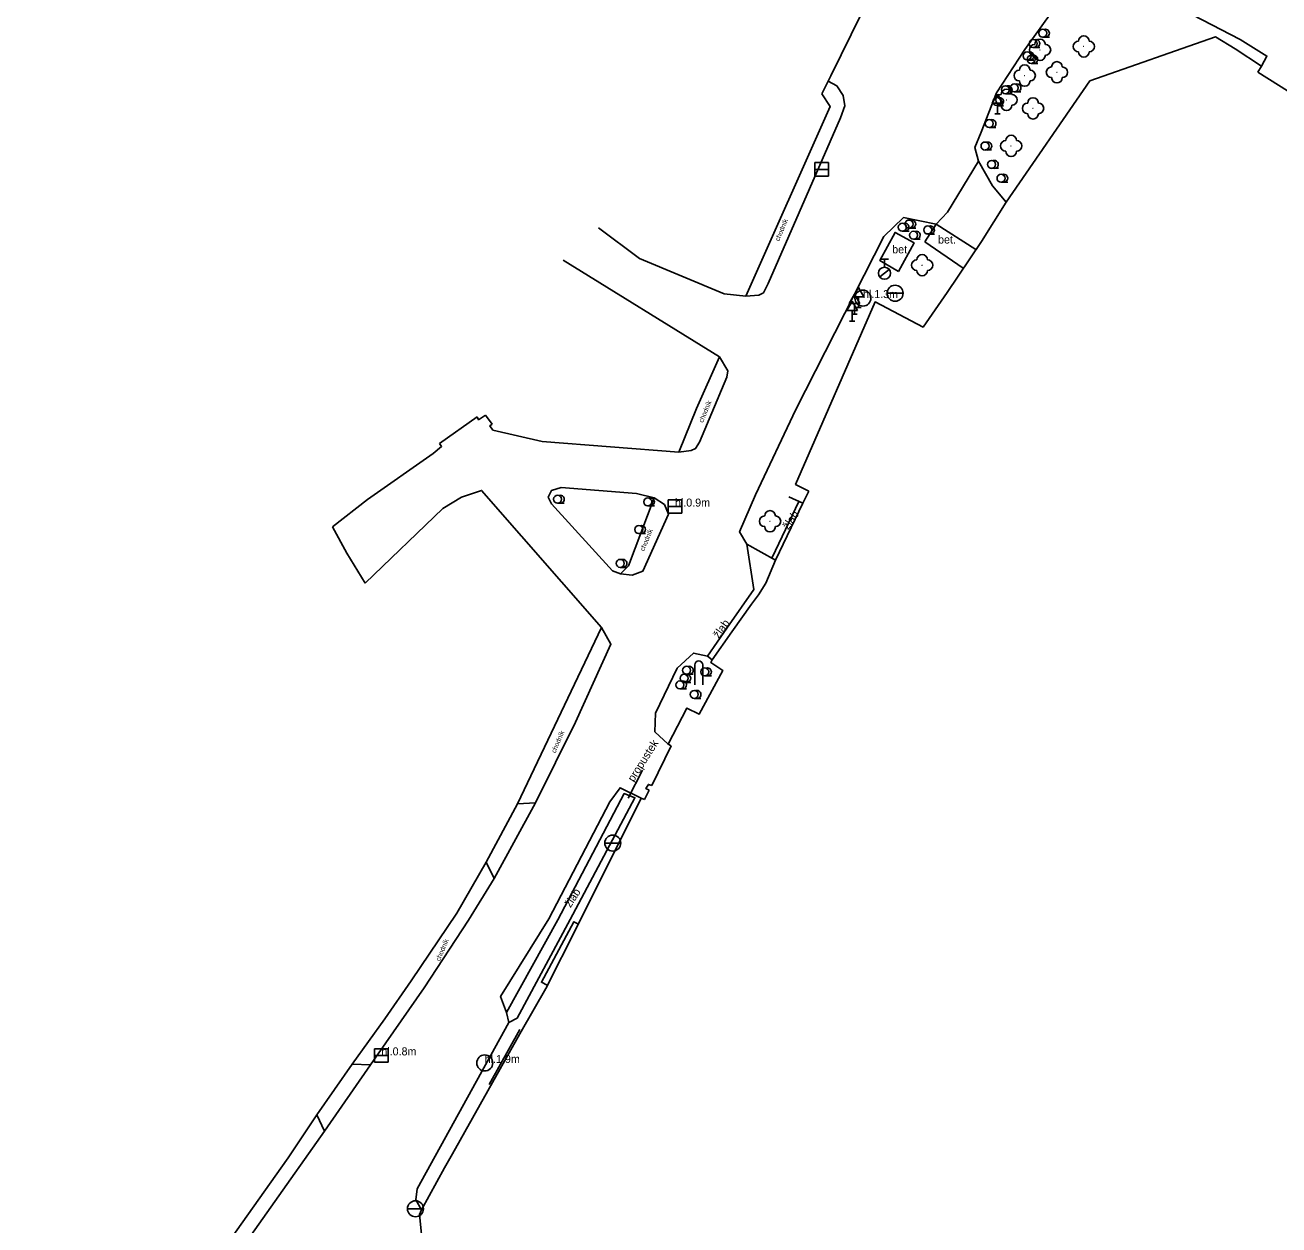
# Model space of a CAD drawing. Extents: x -747135 to -746147, y -1093269 to -1091735.
# Drawn here: x -746683.3 to -746565.8, y -1093037.4 to -1092924.9 of the extents above; entities that cross this region are included whole.
import ezdxf

# ---------------------------------------------------------------- set-up
doc = ezdxf.new("R2010")
doc.units = 0
for name, color, linetype in [('1016', 7, 'Continuous'), ('1029', 7, 'Continuous'), ('105', 7, 'Continuous'), ('23700', 7, 'Continuous'), ('305', 7, 'Continuous'), ('306', 7, 'Continuous'), ('308', 7, 'Continuous'), ('316', 7, 'Continuous'), ('424', 7, 'Continuous'), ('803', 7, 'Continuous')]:
    doc.layers.add(name, color=color, linetype=linetype)

msp = doc.modelspace()

# ---------------------------------------------------------------- linework, layer by layer
at = {"layer": '1016'}
for points in [[(-746567.47, -1092928.76), (-746566.95, -1092927.82), (-746569.47, -1092926.26), (-746577.49, -1092922.09), (-746580.71, -1092921), (-746582.05, -1092920.75), (-746583.67, -1092921.02), (-746585.64, -1092922.33), (-746587.16, -1092923.77), (-746589.64, -1092927.2), (-746592.28, -1092931.27), (-746593.72, -1092934.95), (-746594.32, -1092936.39), (-746593.98, -1092937.68), (-746596.88, -1092942.46), (-746597.95, -1092943.58)], [(-746615.8, -1092950.31), (-746614.56, -1092950.23), (-746614.12, -1092950), (-746613.7, -1092949.12), (-746606.9, -1092933.61), (-746606.5, -1092932.47), (-746606.65, -1092931.53), (-746607.26, -1092930.61), (-746608.07, -1092930.18)], [(-746591.39, -1092941.5), (-746592.66, -1092939.99), (-746593.98, -1092937.68)], [(-746613, -1092975.05), (-746615.68, -1092973.55), (-746616.37, -1092972.41), (-746614.88, -1092968.94), (-746611.1, -1092960.94), (-746602.86, -1092944.72), (-746601.02, -1092942.96), (-746597.95, -1092943.58)], [(-746601.48, -1092948.01), (-746603.24, -1092946.97), (-746601.8, -1092944.35), (-746600.02, -1092945.33), (-746601.48, -1092948.01)], [(-746599.01, -1092945.24), (-746597.95, -1092943.58), (-746594.24, -1092945.95)], [(-746622.08, -1092964.94), (-746620.91, -1092964.8), (-746620.5, -1092964.61), (-746620.13, -1092964), (-746617.56, -1092957.91), (-746617.46, -1092957.32), (-746618.25, -1092956.02)], [(-746633.99, -1092969.78), (-746634.3, -1092969.17), (-746634.01, -1092968.52), (-746633.1, -1092968.24), (-746626.03, -1092968.82), (-746624.39, -1092969.23), (-746626.78, -1092975.58), (-746627.54, -1092976.34), (-746628.27, -1092976.06), (-746633.99, -1092969.78)], [(-746627.54, -1092976.34), (-746626.43, -1092976.48), (-746625.44, -1092976.09), (-746623.04, -1092970.76), (-746623.4, -1092969.86), (-746624.39, -1092969.23)], [(-746672.2, -1093049.79), (-746670.99, -1093050.13), (-746670.38, -1093049.94), (-746655.29, -1093028.58), (-746650.97, -1093022.36), (-746645.93, -1093015.13), (-746641.79, -1093008.8), (-746639.38, -1093004.9), (-746635.51, -1092997.79), (-746631.76, -1092990.25), (-746628.43, -1092982.94), (-746629.31, -1092981.37)], [(-746618.93, -1092984.39), (-746619.38, -1092984.07), (-746620.69, -1092983.77), (-746622.22, -1092985.18), (-746624.25, -1092989.41), (-746624.33, -1092991.14), (-746623.07, -1092992.32)], [(-746625.59, -1092997.36), (-746627.57, -1092996.39), (-746628.53, -1092997.71), (-746634.26, -1093008.66), (-746638.78, -1093015.96), (-746638.22, -1093017.46), (-746637.99, -1093018.4), (-746646.58, -1093033.96), (-746646.72, -1093035), (-746646.19, -1093035.94)], [(-746638.22, -1093017.46), (-746633.4, -1093008.78), (-746627.18, -1092996.94), (-746626.18, -1092997.32), (-746632.26, -1093008.74), (-746637.22, -1093017.99), (-746637.99, -1093018.4)], [(-746637.18, -1092997.91), (-746635.51, -1092997.79)], [(-746639.38, -1093004.9), (-746640.12, -1093003.37)], [(-746652.68, -1093022.3), (-746650.97, -1093022.36)], [(-746655.29, -1093028.58), (-746655.98, -1093027.05)]]:
    msp.add_lwpolyline(points, dxfattribs=at)
at = {"layer": '1029'}
for p, q in [((-746587.96, -1092926.05), (-746587.33, -1092926.05)), ((-746588.86, -1092927.02), (-746588.23, -1092927.02)), ((-746589.42, -1092928.19), (-746588.8, -1092928.19)), ((-746589.05, -1092928.51), (-746588.43, -1092928.51)), ((-746591.46, -1092931.35), (-746590.83, -1092931.35)), ((-746590.63, -1092931.18), (-746590.01, -1092931.18)), ((-746592.26, -1092932.47), (-746591.64, -1092932.47)), ((-746592.97, -1092934.52), (-746592.34, -1092934.52)), ((-746593.37, -1092936.62), (-746592.75, -1092936.62)), ((-746592.75, -1092938.34), (-746592.12, -1092938.34)), ((-746591.87, -1092939.65), (-746591.24, -1092939.65)), ((-746601.12, -1092944.24), (-746600.49, -1092944.24)), ((-746600.49, -1092943.94), (-746599.86, -1092943.94)), ((-746600.07, -1092944.99), (-746599.45, -1092944.99)), ((-746598.74, -1092944.5), (-746598.11, -1092944.5)), ((-746633.43, -1092969.73), (-746632.81, -1092969.73)), ((-746624.98, -1092969.98), (-746624.35, -1092969.98)), ((-746625.82, -1092972.56), (-746625.2, -1092972.56)), ((-746627.56, -1092975.74), (-746626.94, -1092975.74)), ((-746621.58, -1092986.51), (-746620.95, -1092986.51)), ((-746621.34, -1092985.76), (-746620.71, -1092985.76)), ((-746619.64, -1092985.91), (-746619.02, -1092985.91)), ((-746621.97, -1092987.12), (-746621.34, -1092987.12)), ((-746620.62, -1092988.02), (-746619.99, -1092988.02))]:
    msp.add_line(p, q, dxfattribs=at)
for centre in [(-746587.96, -1092925.68), (-746588.86, -1092926.65), (-746589.42, -1092927.81), (-746589.05, -1092928.13), (-746591.46, -1092930.98), (-746590.63, -1092930.8), (-746592.26, -1092932.09), (-746592.97, -1092934.15), (-746593.37, -1092936.25), (-746592.75, -1092937.97), (-746591.87, -1092939.27), (-746600.49, -1092943.56), (-746601.12, -1092943.86), (-746600.07, -1092944.61), (-746598.74, -1092944.12), (-746633.43, -1092969.35), (-746624.98, -1092969.6), (-746625.82, -1092972.19), (-746627.56, -1092975.36), (-746621.34, -1092985.38), (-746619.64, -1092985.53), (-746621.97, -1092986.75), (-746621.58, -1092986.13), (-746620.62, -1092987.64)]:
    msp.add_circle(centre, 0.375, dxfattribs=at)
for centre in [(-746587.71, -1092925.68), (-746588.61, -1092926.65), (-746589.17, -1092927.81), (-746588.8, -1092928.13), (-746591.21, -1092930.98), (-746590.38, -1092930.8), (-746592.01, -1092932.09), (-746592.72, -1092934.15), (-746593.12, -1092936.25), (-746592.5, -1092937.97), (-746591.62, -1092939.27), (-746600.24, -1092943.56), (-746600.87, -1092943.86), (-746599.82, -1092944.61), (-746598.49, -1092944.12), (-746633.18, -1092969.35), (-746624.73, -1092969.6), (-746625.57, -1092972.19), (-746627.31, -1092975.36), (-746621.09, -1092985.38), (-746619.39, -1092985.53), (-746621.72, -1092986.75), (-746621.33, -1092986.13), (-746620.37, -1092987.64)]:
    msp.add_arc(centre, 0.375, 249.4944, 109.0474, dxfattribs=at)
at = {"layer": '23700'}
for points in [[(-746613.31, -1092974.82), (-746610.82, -1092969.57)], [(-746615.68, -1092973.55), (-746615.04, -1092977.8), (-746617.56, -1092981.42), (-746619.38, -1092984.07)], [(-746626.81, -1092997.35), (-746625.46, -1092994.73)], [(-746636.96, -1093019.04), (-746639.85, -1093024.21)]]:
    msp.add_lwpolyline(points, dxfattribs=at)
at = {"layer": '305'}
msp.add_line((-746638.8, -1093022.72), (-746636.83, -1093019.23), dxfattribs=at)
for points in [[(-746607.82, -1092929.66), (-746604.94, -1092923.82)], [(-746608.65, -1092931.35), (-746608.07, -1092930.18)], [(-746563.92, -1092931.77), (-746567.8, -1092929.34)], [(-746644.49, -1092964.14), (-746640.98, -1092961.64)], [(-746640.2, -1092961.46), (-746639.57, -1092962.31)], [(-746610.45, -1092969.72), (-746609.88, -1092968.61)], [(-746651.46, -1092977.21), (-746653.17, -1092974.39)], [(-746613, -1092975.05), (-746613.9, -1092977.22)], [(-746615.25, -1092979.18), (-746614.61, -1092978.32)], [(-746618.93, -1092984.39), (-746617.11, -1092981.79)], [(-746622.78, -1092992.45), (-746624.6, -1092996.18)], [(-746624.84, -1092996.62), (-746625.28, -1092997.5)], [(-746637.18, -1092997.91), (-746640.12, -1093003.37)], [(-746647.15, -1093014.48), (-746649.62, -1093018.03)], [(-746652.68, -1093022.3), (-746655.98, -1093027.05)], [(-746644.02, -1093032.02), (-746643.27, -1093030.71)]]:
    msp.add_lwpolyline(points, dxfattribs=at)
at = {"layer": '306'}
for p, q in [((-746592.2, -1092931.38), (-746592.7, -1092932.25)), ((-746592.2, -1092931.38), (-746591.7, -1092932.25)), ((-746592.7, -1092932.25), (-746591.7, -1092932.25)), ((-746592.2, -1092933.25), (-746592.2, -1092932.25)), ((-746592.45, -1092933.25), (-746591.95, -1092933.25)), ((-746605.6, -1092950.13), (-746606.1, -1092951)), ((-746605.24, -1092949.51), (-746605.74, -1092950.38)), ((-746605.6, -1092950.13), (-746605.1, -1092951)), ((-746605.24, -1092949.51), (-746604.74, -1092950.38)), ((-746605.82, -1092950.79), (-746606.32, -1092951.66)), ((-746606.1, -1092951), (-746605.1, -1092951)), ((-746605.82, -1092950.79), (-746605.32, -1092951.66)), ((-746605.74, -1092950.38), (-746604.74, -1092950.38)), ((-746605.6, -1092952), (-746605.6, -1092951)), ((-746605.49, -1092951.38), (-746604.99, -1092951.38)), ((-746605.24, -1092951.38), (-746605.24, -1092950.38)), ((-746606.32, -1092951.66), (-746605.32, -1092951.66)), ((-746606.07, -1092952.66), (-746605.57, -1092952.66)), ((-746605.85, -1092952), (-746605.35, -1092952)), ((-746605.82, -1092952.66), (-746605.82, -1092951.66)), ((-746620.58, -1092986.75), (-746620.58, -1092984.88)), ((-746619.83, -1092986.75), (-746619.83, -1092984.88))]:
    msp.add_line(p, q, dxfattribs=at)
msp.add_arc((-746620.2, -1092984.88), 0.375, 0, 180, dxfattribs=at)
at = {"layer": '308'}
for p, q in [((-746591.39, -1092941.5), (-746583.56, -1092930.15)), ((-746593.7, -1092945.19), (-746591.39, -1092941.5))]:
    msp.add_line(p, q, dxfattribs=at)
for points in [[(-746596.93, -1092949.97), (-746593.7, -1092945.19)], [(-746651.24, -1092969.39), (-746645.09, -1092965.07)], [(-746610.45, -1092969.72), (-746613, -1092975.05)], [(-746653.17, -1092974.39), (-746654.54, -1092971.93)]]:
    msp.add_lwpolyline(points, dxfattribs=at)
at = {"layer": '316'}
for p, q in [((-746608.05, -1092937.81), (-746609.31, -1092937.81)), ((-746609.31, -1092937.81), (-746609.31, -1092939.07)), ((-746609.31, -1092938.44), (-746608.06, -1092938.44)), ((-746608.05, -1092939.07), (-746608.05, -1092937.81)), ((-746609.31, -1092939.07), (-746608.05, -1092939.07)), ((-746603.23, -1092948.52), (-746602.35, -1092947.82)), ((-746603.17, -1092946.86), (-746602.42, -1092946.86)), ((-746602.79, -1092947.61), (-746602.79, -1092946.86)), ((-746601.05, -1092950.05), (-746602.55, -1092950.05)), ((-746621.8, -1092969.41), (-746623.06, -1092969.41)), ((-746623.06, -1092969.41), (-746623.06, -1092970.67)), ((-746623.06, -1092970.04), (-746621.81, -1092970.04)), ((-746621.8, -1092970.67), (-746621.8, -1092969.41)), ((-746623.06, -1092970.67), (-746621.8, -1092970.67)), ((-746627.51, -1093001.57), (-746629.01, -1093001.57)), ((-746649.32, -1093020.84), (-746650.58, -1093020.84)), ((-746650.58, -1093020.84), (-746650.58, -1093022.1)), ((-746649.32, -1093022.1), (-746649.32, -1093020.84)), ((-746650.58, -1093021.47), (-746649.33, -1093021.47)), ((-746650.58, -1093022.1), (-746649.32, -1093022.1)), ((-746646, -1093035.84), (-746647.5, -1093035.84))]:
    msp.add_line(p, q, dxfattribs=at)
for centre, radius in [((-746602.79, -1092948.17), 0.562), ((-746604.81, -1092950.5), 0.75), ((-746640.26, -1093022.18), 0.75)]:
    msp.add_circle(centre, radius, dxfattribs=at)
for centre, start, end in [((-746601.8, -1092950.05), 0, 180), ((-746601.8, -1092950.05), 180, 0), ((-746628.26, -1093001.57), 0, 180), ((-746628.26, -1093001.57), 180, 0), ((-746646.75, -1093035.84), 0, 180), ((-746646.75, -1093035.84), 180, 0)]:
    msp.add_arc(centre, 0.747, start, end, dxfattribs=at)
at = {"layer": '424'}
msp.add_lwpolyline([(-746634.41, -1093014.9), (-746634.94, -1093014.62), (-746631.9, -1093008.94), (-746631.47, -1093009.17)], dxfattribs=at)
for centre in [(-746588.21, -1092927.24), (-746584.11, -1092926.92), (-746589.65, -1092929.65), (-746586.63, -1092929.34), (-746591.35, -1092931.93), (-746588.87, -1092932.72), (-746590.92, -1092936.24), (-746599.26, -1092947.42), (-746613.52, -1092971.42)]:
    msp.add_circle(centre, 0.0005, dxfattribs=at)
for centre, start, end in [((-746588.71, -1092927.24), 90, 270), ((-746588.21, -1092926.74), 0, 180), ((-746587.71, -1092927.24), 270, 90), ((-746584.61, -1092926.92), 90, 270), ((-746584.11, -1092926.42), 0, 180), ((-746583.61, -1092926.92), 270, 90), ((-746588.21, -1092927.74), 180, 360), ((-746584.11, -1092927.42), 180, 360), ((-746590.15, -1092929.65), 90, 270), ((-746589.65, -1092929.15), 0, 180), ((-746589.15, -1092929.65), 270, 90), ((-746587.13, -1092929.34), 90, 270), ((-746586.63, -1092928.84), 0, 180), ((-746586.13, -1092929.34), 270, 90), ((-746589.65, -1092930.15), 180, 360), ((-746586.63, -1092929.84), 180, 360), ((-746591.85, -1092931.93), 90, 270), ((-746591.35, -1092931.43), 0, 180), ((-746590.85, -1092931.93), 270, 90), ((-746591.35, -1092932.43), 180, 360), ((-746589.37, -1092932.72), 90, 270), ((-746588.87, -1092932.22), 0, 180), ((-746588.37, -1092932.72), 270, 90), ((-746588.87, -1092933.22), 180, 360), ((-746591.42, -1092936.24), 90, 270), ((-746590.92, -1092935.74), 0, 180), ((-746590.42, -1092936.24), 270, 90), ((-746590.92, -1092936.74), 180, 360), ((-746599.26, -1092946.92), 0, 180), ((-746599.76, -1092947.42), 90, 270), ((-746599.26, -1092947.92), 180, 360), ((-746598.76, -1092947.42), 270, 90), ((-746614.02, -1092971.42), 90, 270), ((-746613.52, -1092970.92), 0, 180), ((-746613.02, -1092971.42), 270, 90), ((-746613.52, -1092971.92), 180, 360)]:
    msp.add_arc(centre, 0.5, start, end, dxfattribs=at)
at = {"layer": '803'}
for points in [[(-746567.8, -1092929.34), (-746567.47, -1092928.76), (-746569.93, -1092927.14), (-746571.76, -1092926.03), (-746583.56, -1092930.15)], [(-746608.07, -1092930.18), (-746607.82, -1092929.66)], [(-746629.61, -1092943.93), (-746625.76, -1092946.8), (-746617.81, -1092950.11), (-746615.8, -1092950.31), (-746607.89, -1092932.54), (-746608.65, -1092931.35)], [(-746599.01, -1092945.24), (-746595.41, -1092947.69)], [(-746639.49, -1092962.88), (-746634.89, -1092963.93), (-746622.08, -1092964.94), (-746620.4, -1092960.85), (-746618.25, -1092956.02), (-746632.9, -1092946.96)], [(-746596.93, -1092949.97), (-746599.18, -1092953.22), (-746603.68, -1092950.86), (-746611.12, -1092967.97), (-746609.88, -1092968.61)], [(-746640.98, -1092961.64), (-746640.84, -1092961.9), (-746640.2, -1092961.46)], [(-746639.57, -1092962.31), (-746639.77, -1092962.47), (-746639.49, -1092962.88)], [(-746645.09, -1092965.07), (-746644.31, -1092964.4), (-746644.49, -1092964.14)], [(-746651.46, -1092977.21), (-746644.17, -1092970.22), (-746642.43, -1092969.17), (-746640.56, -1092968.53), (-746629.31, -1092981.37), (-746637.18, -1092997.91)], [(-746610.45, -1092969.72), (-746611.75, -1092969.12)], [(-746654.54, -1092971.93), (-746651.24, -1092969.39)], [(-746613.9, -1092977.22), (-746614.61, -1092978.32)], [(-746617.11, -1092981.79), (-746615.25, -1092979.18)], [(-746618.93, -1092984.39), (-746619.08, -1092984.64), (-746617.94, -1092985.41), (-746620.16, -1092989.48), (-746621.31, -1092988.92), (-746623.07, -1092992.32), (-746622.78, -1092992.45)], [(-746624.6, -1092996.18), (-746624.91, -1092996.07), (-746625.15, -1092996.46), (-746624.84, -1092996.62)], [(-746625.28, -1092997.5), (-746625.59, -1092997.36), (-746631.56, -1093009.33)], [(-746640.12, -1093003.37), (-746642.87, -1093008.13), (-746647.15, -1093014.48)], [(-746636.83, -1093019.23), (-746634.54, -1093015.21), (-746631.56, -1093009.33)], [(-746649.62, -1093018.03), (-746652.68, -1093022.3)], [(-746643.27, -1093030.71), (-746638.8, -1093022.72)], [(-746655.98, -1093027.05), (-746658.67, -1093031.07)], [(-746683.34, -1093039.76), (-746675.31, -1093048.73), (-746674.15, -1093049.62), (-746673, -1093049.94), (-746672.2, -1093049.79), (-746671.6, -1093049.27), (-746658.67, -1093031.07)], [(-746644.69, -1093054.86), (-746645.95, -1093040.73), (-746646.37, -1093036.39), (-746646.19, -1093035.94), (-746644.02, -1093032.02)]]:
    msp.add_lwpolyline(points, dxfattribs=at)

# ---------------------------------------------------------------- texts
at = {"layer": '105'}
for s, height, rotation, p in [('chodník', 0.45, 67.0213, (-746612.67, -1092945.21)), ('bet.', 0.75, 0.0578, (-746602.07, -1092946.31)), ('bet.', 0.75, 0.0578, (-746597.77, -1092945.39)), ('chodník', 0.45, 67.0213, (-746619.82, -1092962.22)), ('žlab', 0.75, 54.6731, (-746611.82, -1092972.26)), ('chodník', 0.45, 67.0213, (-746625.33, -1092974.26)), ('žlab', 0.75, 54.6731, (-746618.32, -1092982.45)), ('chodník', 0.45, 67.0213, (-746633.63, -1092993.17)), ('propustek', 0.75, 57.4265, (-746626.31, -1092995.9)), ('žlab', 0.75, 57.4265, (-746632.22, -1093007.68)), ('chodník', 0.45, 67.0213, (-746644.47, -1093012.68))]:
    msp.add_text(s, height=height, rotation=rotation, dxfattribs=at).set_placement(p)
for s, p in [('hl.1.3m', (-746604.81, -1092950.5)), ('hl.0.9m', (-746622.43, -1092970.04)), ('hl.0.8m', (-746649.95, -1093021.47)), ('hl.1.9m', (-746640.26, -1093022.18))]:
    msp.add_text(s, height=0.75, dxfattribs=at).set_placement(p)

doc.saveas('drawing.dxf')
